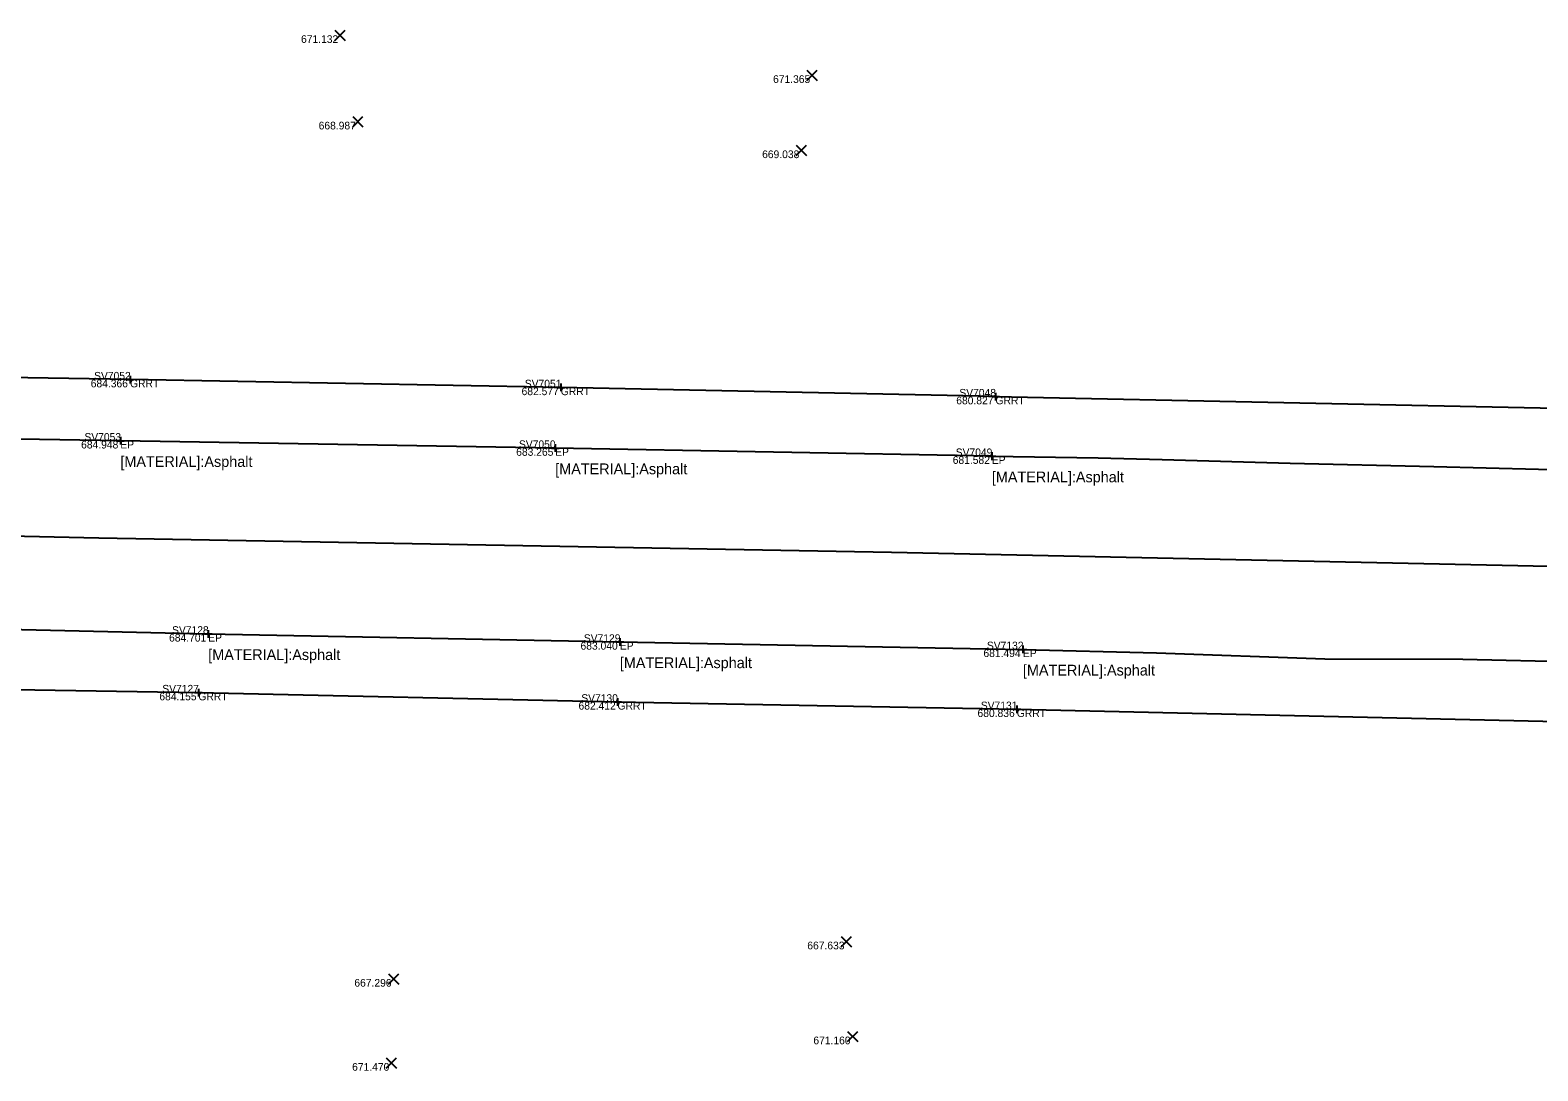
# Model space of a CAD drawing. Extents: x 1659932 to 1663108, y 619867 to 620611.
# Drawn here: x 1661986.7 to 1662182.6, y 620149.4 to 620284.7 of the extents above; entities that cross this region are included whole.
import ezdxf

# ---------------------------------------------------------------- set-up
doc = ezdxf.new("R2010")
doc.units = 0
for name, color, linetype in [('PM_X_CL_Dashed', 7, 'Continuous'), ('PV_X_EOP', 7, 'Continuous'), ('RD_X_GR_Lt', 7, 'Continuous'), ('RD_X_GR_Rt', 7, 'Continuous'), ('SV_X_Random_Point', 7, 'Continuous'), ('SV_X_Shot_Marker', 7, 'Continuous'), ('SV_X_Text', 7, 'Continuous'), ('SV_X_Text_Comment', 7, 'Continuous'), ('SV_X_Text_Elevation', 7, 'Continuous'), ('SV_X_Text_Name', 7, 'Continuous')]:
    doc.layers.add(name, color=color, linetype=linetype)

msp = doc.modelspace()

# ---------------------------------------------------------------- linework, layer by layer
at = {"layer": 'PM_X_CL_Dashed'}
msp.add_lwpolyline([(1661548.68, 620227.77), (1661669.96, 620225.42), (1661783.14, 620222.83), (1661893.22, 620220.99), (1661995.64, 620218.69), (1662098.65, 620216.83), (1662208.49, 620214.49), (1662310.47, 620212.73), (1662401.36, 620210.77), (1662501.77, 620209.17), (1662614.52, 620207.13), (1662727.83, 620205.67), (1662841.02, 620204.32), (1662955.43, 620202.56), (1663049.21, 620201.36)], dxfattribs=at)
at = {"layer": 'PV_X_EOP'}
for points in [[(1662111.67, 620229.32), (1662054.93, 620230.37), (1661998.42, 620231.32), (1661945.73, 620232.16), (1661885.47, 620233.5), (1661831.11, 620234.65), (1661773.24, 620235.9), (1661719.2, 620236.82), (1661662.34, 620238.11), (1661602.46, 620239.35), (1661551.29, 620241.52)], [(1662111.67, 620229.32), (1662125.47, 620229.12), (1662133.82, 620228.89), (1662150.43, 620228.4), (1662169.11, 620227.96), (1662189.5, 620227.46), (1662215.41, 620227.19), (1662252.56, 620226.73), (1662280.57, 620225.7), (1662300.84, 620225.1), (1662313.97, 620225.05), (1662336.92, 620224.59), (1662356.1, 620223.94), (1662379.4, 620223.45)], [(1661543.6, 620215.08), (1661595.45, 620214.35), (1661653.94, 620213.41), (1661707.72, 620212.24), (1661760.97, 620211.02), (1661840.69, 620209.32), (1661897.28, 620208.31), (1661955.8, 620207.5), (1662009.84, 620206.22), (1662063.33, 620205.17), (1662115.71, 620204.21)], [(1662115.71, 620204.21), (1662133.08, 620203.78), (1662154.95, 620202.99), (1662172.89, 620202.94), (1662187.93, 620202.58), (1662221, 620201.66), (1662242.3, 620201.13), (1662265.55, 620200.91), (1662285.71, 620200.45), (1662300.86, 620200.19), (1662310.53, 620199.87), (1662321.29, 620199.41), (1662341.04, 620198.87), (1662354.07, 620198.82), (1662368.44, 620198.38), (1662381.78, 620198.56)]]:
    msp.add_lwpolyline(points, dxfattribs=at)
at = {"layer": 'RD_X_GR_Lt'}
msp.add_line((1662112.15, 620237.06), (1662445.65, 620230.14), dxfattribs=at)
at = {"layer": 'RD_X_GR_Rt'}
msp.add_line((1662114.92, 620196.42), (1662378.55, 620190.5), dxfattribs=at)
for points in [[(1662112.15, 620237.06), (1662055.66, 620238.25), (1661999.68, 620239.27), (1661943.73, 620240.2), (1661887.33, 620241.47), (1661831.01, 620242.22), (1661774.89, 620243.8), (1661718.6, 620244.37), (1661662.44, 620245.38), (1661601.89, 620244.64), (1661537.84, 620244.62)], [(1661527.71, 620211.76), (1661596.63, 620209.07), (1661652.77, 620205.71), (1661709.09, 620204.45), (1661758.9, 620203.47), (1661840.54, 620201.81), (1661896.27, 620200.97), (1661955.33, 620199.48), (1662008.56, 620198.59), (1662063.03, 620197.38), (1662114.92, 620196.42)]]:
    msp.add_lwpolyline(points, dxfattribs=at)
at = {"layer": 'SV_X_Random_Point'}
for p, q in [((1662026.31, 620283.36), (1662027.64, 620284.69)), ((1662026.31, 620284.69), (1662027.64, 620283.36)), ((1662087.64, 620278.16), (1662088.98, 620279.5)), ((1662087.64, 620279.5), (1662088.98, 620278.16)), ((1662028.62, 620272.12), (1662029.95, 620273.45)), ((1662028.62, 620273.45), (1662029.95, 620272.12)), ((1662086.25, 620268.39), (1662087.58, 620269.73)), ((1662086.25, 620269.73), (1662087.58, 620268.39)), ((1662092.09, 620165.55), (1662093.42, 620166.88)), ((1662092.09, 620166.88), (1662093.42, 620165.55)), ((1662033.27, 620160.7), (1662034.6, 620162.03)), ((1662033.27, 620162.03), (1662034.6, 620160.7)), ((1662092.93, 620153.22), (1662094.26, 620154.55)), ((1662092.93, 620154.55), (1662094.26, 620153.22)), ((1662032.98, 620149.77), (1662034.32, 620151.11)), ((1662032.98, 620151.11), (1662034.32, 620149.77))]:
    msp.add_line(p, q, dxfattribs=at)
at = {"layer": 'SV_X_Shot_Marker'}
for p, q in [((1661999.18, 620239.27), (1662000.18, 620239.27)), ((1661999.68, 620239.77), (1661999.68, 620238.77)), ((1661999.68, 620239.27), (1661999.68, 620239.27)), ((1662055.16, 620238.25), (1662056.16, 620238.25)), ((1662055.66, 620238.75), (1662055.66, 620237.75)), ((1662055.66, 620238.25), (1662055.66, 620238.25)), ((1662112.15, 620237.56), (1662112.15, 620236.56)), ((1662111.65, 620237.06), (1662112.65, 620237.06)), ((1662112.15, 620237.06), (1662112.15, 620237.06)), ((1661998.42, 620231.82), (1661998.42, 620230.82)), ((1661997.92, 620231.32), (1661998.92, 620231.32)), ((1661998.42, 620231.32), (1661998.42, 620231.32)), ((1662054.43, 620230.37), (1662055.43, 620230.37)), ((1662054.93, 620230.87), (1662054.93, 620229.87)), ((1662054.93, 620230.37), (1662054.93, 620230.37)), ((1662111.67, 620229.82), (1662111.67, 620228.82)), ((1662111.17, 620229.32), (1662112.17, 620229.32)), ((1662111.67, 620229.32), (1662111.67, 620229.32)), ((1662009.34, 620206.22), (1662010.34, 620206.22)), ((1662009.84, 620206.72), (1662009.84, 620205.72)), ((1662009.84, 620206.22), (1662009.84, 620206.22)), ((1662062.83, 620205.17), (1662063.83, 620205.17)), ((1662063.33, 620205.67), (1662063.33, 620204.67)), ((1662063.33, 620205.17), (1662063.33, 620205.17)), ((1662115.21, 620204.21), (1662116.21, 620204.21)), ((1662115.71, 620204.71), (1662115.71, 620203.71)), ((1662115.71, 620204.21), (1662115.71, 620204.21)), ((1662008.06, 620198.59), (1662009.06, 620198.59)), ((1662008.56, 620199.09), (1662008.56, 620198.09)), ((1662008.56, 620198.59), (1662008.56, 620198.59)), ((1662062.53, 620197.38), (1662063.53, 620197.38)), ((1662063.03, 620197.88), (1662063.03, 620196.88)), ((1662063.03, 620197.38), (1662063.03, 620197.38)), ((1662114.42, 620196.42), (1662115.42, 620196.42)), ((1662114.92, 620196.92), (1662114.92, 620195.92)), ((1662114.92, 620196.42), (1662114.92, 620196.42))]:
    msp.add_line(p, q, dxfattribs=at)

# ---------------------------------------------------------------- texts
at = {"layer": 'SV_X_Text'}
for p in [(1661998.42, 620227.92), (1662054.93, 620226.97), (1662111.67, 620225.92), (1662009.84, 620202.82), (1662063.33, 620201.77), (1662115.71, 620200.81)]:
    msp.add_text('[MATERIAL]:Asphalt', height=1.4, dxfattribs=at).set_placement(p)
at = {"layer": 'SV_X_Text_Comment'}
for s, p in [('GRRT', (1661999.68, 620238.27)), ('GRRT', (1662055.66, 620237.25)), ('GRRT', (1662112.15, 620236.06)), ('EP', (1661998.42, 620230.32)), ('EP', (1662054.93, 620229.37)), ('EP', (1662111.67, 620228.32)), ('EP', (1662009.84, 620205.22)), ('EP', (1662063.33, 620204.17)), ('EP', (1662115.71, 620203.21)), ('GRRT', (1662008.56, 620197.59)), ('GRRT', (1662063.03, 620196.38)), ('GRRT', (1662114.92, 620195.42))]:
    msp.add_text(s, height=1, dxfattribs=at).set_placement(p)
at = {"layer": 'SV_X_Text_Elevation'}
for s, p in [('671.132', (1662021.9, 620283.03)), ('671.365', (1662083.24, 620277.83)), ('668.987', (1662024.19, 620271.79)), ('669.038', (1662081.82, 620268.06)), ('684.366', (1661994.57, 620238.27)), ('682.577', (1662050.56, 620237.25)), ('680.827', (1662107.05, 620236.06)), ('684.948', (1661993.32, 620230.32)), ('683.265', (1662049.86, 620229.37)), ('681.582', (1662106.59, 620228.32)), ('684.701', (1662004.75, 620205.22)), ('683.040', (1662058.22, 620204.17)), ('681.494', (1662110.58, 620203.21)), ('684.155', (1662003.49, 620197.59)), ('682.412', (1662057.96, 620196.38)), ('680.836', (1662109.81, 620195.42)), ('667.633', (1662087.69, 620165.22)), ('667.296', (1662028.83, 620160.37)), ('671.160', (1662088.48, 620152.88)), ('671.470', (1662028.54, 620149.44))]:
    msp.add_text(s, height=1, dxfattribs=at).set_placement(p)
at = {"layer": 'SV_X_Text_Name'}
for s, p in [('SV7052', (1661995.01, 620239.27)), ('SV7051', (1662050.98, 620238.25)), ('SV7048', (1662107.45, 620237.06)), ('SV7053', (1661993.75, 620231.32)), ('SV7050', (1662050.22, 620230.37)), ('SV7049', (1662106.98, 620229.32)), ('SV7128', (1662005.14, 620206.22)), ('SV7129', (1662058.65, 620205.17)), ('SV7132', (1662111.03, 620204.21)), ('SV7127', (1662003.87, 620198.59)), ('SV7130', (1662058.32, 620197.38)), ('SV7131', (1662110.24, 620196.42))]:
    msp.add_text(s, height=1, dxfattribs=at).set_placement(p)

doc.saveas('drawing.dxf')
